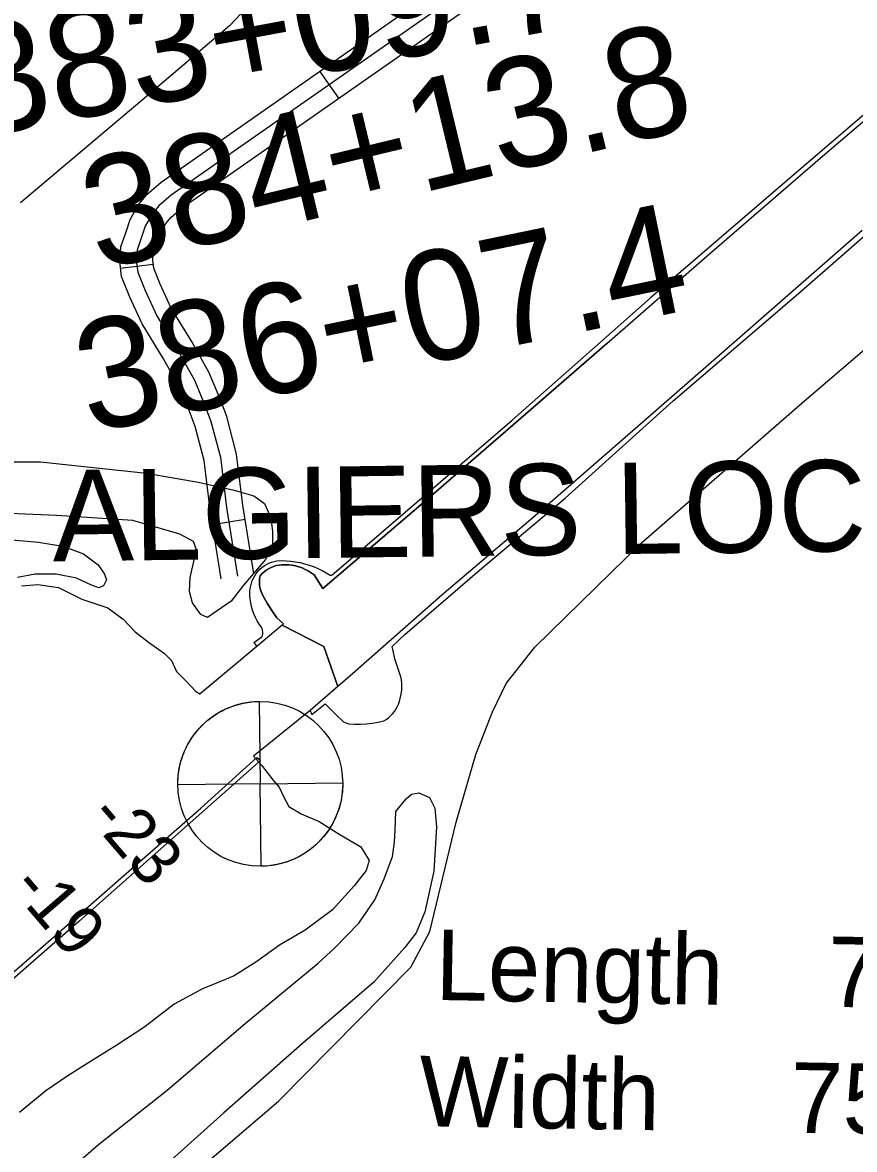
# Model space of a CAD drawing. Extents: x 3704301 to 3742427, y 506229 to 532009.
# Drawn here: x 3711457 to 3712214, y 516437 to 517461 of the extents above; entities that cross this region are included whole.
import ezdxf

# ---------------------------------------------------------------- set-up
doc = ezdxf.new("R2010")
doc.units = 0
for name, color, linetype in [('V-LEVE-TOET', 7, 'Continuous'), ('V-RIVR-GAGE', 7, 'Continuous'), ('V-RIVR-IDEN', 7, 'Continuous'), ('V-ROAD-CNTR', 7, 'Continuous'), ('V-SITE-VEGE', 7, 'Continuous'), ('V-SURV-IDEN', 7, 'Continuous'), ('V-TOPO-SHOR', 7, 'Continuous'), ('V-TOPO-SPOT', 7, 'Continuous'), ('V-TRAN-LOCK', 7, 'Continuous')]:
    doc.layers.add(name, color=color, linetype=linetype)

msp = doc.modelspace()

# ---------------------------------------------------------------- linework, layer by layer
at = {"layer": 'V-LEVE-TOET'}
for points in [[(3711361.398, 517061.842), (3711473.166, 517061.69), (3711569.7060000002, 517051.651), (3711616.72, 517043.39400000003), (3711648.083, 517036.238), (3711667.363, 517030.829), (3711677.003, 517024.028), (3711682.733, 517010.77900000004), (3711684.282, 516998.579), (3711684.427, 516986.416), (3711677.992, 516973.02400000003), (3711657.965, 516949.753), (3711646.588, 516935.042), (3711625.1520000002, 516920.17600000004), (3711619.149, 516923.139), (3711611.477, 516933.63300000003), (3711608.946, 516943.988), (3711609.2800000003, 516956.60500000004), (3711611.901, 516967.292), (3711615.088, 516981.706), (3711612.483, 516989.257), (3711600.037, 516996.134), (3711557.339, 517008.487), (3711487.7800000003, 517013.134), (3711360.716, 517018.369)], [(3711424.006, 516352.617), (3711525.9590000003, 516441.114), (3711588.528, 516490.434), (3711659.3510000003, 516551.224), (3711725.807, 516606.053), (3711740.665, 516619.691), (3711762.782, 516642.487), (3711777.372, 516663.614), (3711785.822, 516682.565), (3711793.377, 516702.94200000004), (3711795.126, 516715.99), (3711795.89, 516727.195), (3711796.3340000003, 516744.01900000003), (3711805.99, 516755.455), (3711810.774, 516759.537), (3711817.355, 516760.765), (3711827.0700000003, 516756.766), (3711831.951, 516746.816), (3711833.3740000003, 516729.943), (3711830.9080000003, 516689.79000000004), (3711822.911, 516652.588), (3711814.926, 516633.626), (3711804.751, 516620.332), (3711776.325, 516588.815), (3711711.715, 516533.003), (3711639.895, 516469.9), (3711568.039, 516405.392)]]:
    msp.add_lwpolyline(points, dxfattribs=at)
at = {"layer": 'V-RIVR-GAGE'}
for points in [[(3711672.2740780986, 516844.07543143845), (3711673.188, 516769.081), (3711598.1935685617, 516768.16707809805), (3711598.197927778, 516770.27128745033), (3711598.282565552, 516772.84550994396), (3711598.493100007, 516775.8392977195), (3711598.821027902, 516778.80151366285), (3711599.2362403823, 516781.57677934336), (3711599.802894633, 516784.5629060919), (3711600.397397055, 516787.1513426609), (3711601.0304314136, 516789.5322333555), (3711601.760019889, 516791.9503033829), (3711602.696632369, 516794.6959204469), (3711603.5989879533, 516797.05209115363), (3711604.575825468, 516799.36916656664), (3711605.74128479, 516801.8825550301), (3711607.1371678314, 516804.60876715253), (3711608.455638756, 516806.95800797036), (3711609.8253245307, 516809.20786549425), (3711612.1858010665, 516812.7118895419), (3711613.8535987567, 516814.954379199), (3711616.0418616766, 516817.6542450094), (3711618.1569687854, 516820.03819591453), (3711619.9720573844, 516821.92945432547), (3711622.707339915, 516824.5489799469), (3711625.021880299, 516826.57033414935), (3711627.4552527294, 516828.5241313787), (3711630.5400670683, 516830.7738888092), (3711632.8971613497, 516832.3397277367), (3711635.465288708, 516833.9041381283), (3711638.420619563, 516835.53627186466), (3711641.0428870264, 516836.8433228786), (3711643.619900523, 516838.0068117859), (3711647.233619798, 516839.4469541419), (3711650.461352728, 516840.5553683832), (3711653.624259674, 516841.4849794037), (3711656.8687691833, 516842.2835750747), (3711660.2607910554, 516842.9589591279), (3711664.3058490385, 516843.5532948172), (3711667.291471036, 516843.84869842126), (3711669.8357466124, 516844.0057136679)], [(3711674.1019219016, 516694.0865685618), (3711673.188, 516769.081), (3711748.1824314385, 516769.9949219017), (3711748.1677877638, 516767.3395463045), (3711748.0273076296, 516764.1775996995), (3711747.8129110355, 516761.5827944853), (3711747.5036555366, 516758.9758324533), (3711747.0107994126, 516755.842594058), (3711746.4073916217, 516752.8360179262), (3711745.5879239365, 516749.50478486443), (3711744.9711220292, 516747.3511088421), (3711744.039971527, 516744.48554943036), (3711742.954575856, 516741.55710577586), (3711741.8916573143, 516738.99996358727), (3711740.738111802, 516736.49372083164), (3711739.491097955, 516734.02534191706), (3711738.178955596, 516731.64917621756), (3711736.5742228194, 516728.9914242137), (3711735.1053372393, 516726.75735905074), (3711733.02345498, 516723.8627750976), (3711730.9196861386, 516721.2049420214), (3711728.3305605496, 516718.24517215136), (3711726.0690134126, 516715.89643939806), (3711723.613273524, 516713.56234137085), (3711721.4570883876, 516711.67692691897), (3711719.83312458, 516710.3510394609), (3711717.2062296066, 516708.35688104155), (3711715.3112859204, 516707.0276912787), (3711712.8148844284, 516705.4041505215), (3711710.1738112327, 516703.83485087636), (3711707.4743774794, 516702.376848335), (3711705.365915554, 516701.33507805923), (3711703.109257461, 516700.30850304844), (3711700.508161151, 516699.2337272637), (3711697.811097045, 516698.2377879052), (3711694.5506475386, 516697.1879793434), (3711691.4019108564, 516696.3265460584), (3711688.979610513, 516695.761986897), (3711686.2309688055, 516695.22345299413), (3711683.8494353, 516694.842404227), (3711681.065456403, 516694.49545394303), (3711678.871715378, 516694.2967070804), (3711676.3033684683, 516694.1453989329)]]:
    msp.add_lwpolyline(points, close=True, dxfattribs=at)
msp.add_circle((3711673.188014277, 516769.0810236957), 74.99999999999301, dxfattribs=at)
at = {"layer": 'V-ROAD-CNTR'}
for p, q in [((3711727.190506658, 517416.9751398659), (3711744.3884722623, 517392.394189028)), ((3711546.105868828, 517237.8744980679), (3711575.8698093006, 517241.63449054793)), ((3711629.7847014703, 517004.91496398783), (3711659.4076422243, 517009.65495450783))]:
    msp.add_line(p, q, dxfattribs=at)
for points in [[(3711637.68468567, 516955.543062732), (3711627.6517057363, 517018.24493732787), (3711622.1367167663, 517063.14184753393), (3711614.017733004, 517094.01678578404), (3711608.6527437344, 517108.5667566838), (3711599.7897614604, 517129.44271493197), (3711585.27479049, 517155.3806630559), (3711565.721829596, 517187.4015990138), (3711554.640851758, 517211.5785506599), (3711547.0558669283, 517230.35551310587), (3711545.30487043, 517244.21448538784), (3711546.278868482, 517257.2484593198), (3711551.097858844, 517270.99743182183), (3711554.8598513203, 517282.25940929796), (3711562.418836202, 517295.445382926), (3711570.0708208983, 517304.9013640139), (3711583.017795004, 517316.10834159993), (3711893.106174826, 517533.05490770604)], [(3711901.7051576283, 517520.7639322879), (3711592.24977654, 517304.2603652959), (3711580.8937992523, 517294.43138495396), (3711574.83481137, 517286.94339993), (3711568.6148238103, 517276.09242163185), (3711565.28983046, 517266.140441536), (3711561.08983886, 517254.15646550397), (3711560.375840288, 517244.59948461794), (3711561.6938376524, 517234.167505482), (3711568.4198242, 517217.51553878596), (3711578.9868030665, 517194.459584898), (3711598.2257645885, 517162.954647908), (3711613.277734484, 517136.0557017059), (3711622.601715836, 517114.09574562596), (3711628.340704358, 517098.52877675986), (3711636.901687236, 517065.9768418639), (3711642.5066760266, 517020.34493312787), (3711652.496656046, 516957.913057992)], [(3711667.308626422, 516960.283053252), (3711657.361646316, 517022.44492892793), (3711651.6666577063, 517068.81183619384), (3711642.663675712, 517103.040767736), (3711636.550687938, 517119.6247345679), (3711626.765707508, 517142.6686884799), (3711611.1767386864, 517170.5286327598), (3711592.251776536, 517201.5175707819), (3711582.1987966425, 517223.452526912), (3711576.3318083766, 517237.9794978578), (3711575.4468101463, 517244.98448384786), (3711575.9008092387, 517251.06447168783), (3711579.4818020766, 517261.2834512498), (3711582.3697963, 517269.9254339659), (3711587.2507865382, 517278.441416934), (3711591.716777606, 517283.9614058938), (3711601.481758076, 517292.41238899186), (3711910.30414043, 517508.47295686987)]]:
    msp.add_lwpolyline(points, dxfattribs=at)
at = {"layer": 'V-SITE-VEGE'}
for points in [[(3711455.682, 517839.613), (3711703.711, 517815.229), (3711879.18, 517797.80700000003), (3711910.707, 517793.721), (3711923.197, 517792.56), (3711932.123, 517789.61100000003), (3711937.492, 517783.67600000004), (3711938.095, 517779.514), (3711930.992, 517765.22500000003), (3711904.88, 517743.16000000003), (3711768.995, 517620.93), (3711706.679, 517569.045), (3711704.313, 517563.688), (3711703.1520000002, 517551.791), (3711704.967, 517539.309), (3711700.238, 517526.216), (3711677.13, 517492.264), (3711645.099, 517458.292), (3711569.731, 517393.88800000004), (3711455.1920000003, 517297.28)], [(3711524.872, 516339.63300000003), (3711689.684, 516480.636), (3711809.984, 516602.387), (3711827.347, 516634.928), (3711851.186, 516734.09), (3711869.3170000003, 516795.684), (3711884.49, 516834.571), (3711896.954, 516860.17100000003), (3711922.974, 516893.271), (3712019.7770000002, 516988.141), (3712166.154, 517115.489), (3712235.302, 517174.947)], [(3711447.1010000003, 516991.063), (3711471.486, 516988.743), (3711493.498, 516985.228), (3711512.545, 516978.13800000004), (3711525.65, 516968.06), (3711531.6180000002, 516959.751), (3711533.414, 516954.402), (3711530.452, 516949.042), (3711526.2970000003, 516947.248), (3711519.748, 516949.609), (3711506.055, 516956.12), (3711487.612, 516959.645), (3711468.5840000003, 516959.598), (3711452.534, 516956.587)]]:
    msp.add_lwpolyline(points, dxfattribs=at)
at = {"layer": 'V-TOPO-SHOR'}
for points in [[(3711456.049, 516949.001), (3711470.915, 516950.38800000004), (3711489.818, 516947.514), (3711510.89, 516936.873), (3711534.411, 516929.134), (3711548.37, 516918.681), (3711559.333, 516907.12), (3711571.546, 516897.89900000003), (3711586.097, 516887.43), (3711592.46, 516881.331), (3711596.935, 516871.13), (3711606.183, 516861.988), (3711614.2630000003, 516853.47000000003), (3711618.348, 516850.99), (3711618.498, 516850.84500000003)], [(3711731.011, 516894.037), (3711693.1070000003, 516913.362), (3711670.171, 516893.908), (3711618.498, 516850.84500000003)], [(3711731.011, 516894.037), (3711743.762, 516857.511), (3711718.412, 516835.73000000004), (3711666.995, 516794.148)], [(3711666.995, 516794.148), (3711674.165, 516786.04600000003), (3711684.489, 516772.724), (3711690.241, 516766.047), (3711694.1720000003, 516757.63800000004), (3711699.271, 516748.606), (3711710.361, 516741.789), (3711726.784, 516734.83), (3711745.453, 516723.066), (3711764.7290000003, 516711.88), (3711772.106, 516699.227), (3711769.4990000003, 516690.4), (3711758.454, 516676.457), (3711738.892, 516654.435), (3711714.088, 516636.112), (3711690.596, 516622.499), (3711670.034, 516607.62), (3711649.521, 516594.521), (3711633.33, 516587.832), (3711620.741, 516582.827), (3711594.862, 516568.683), (3711568.218, 516548.036), (3711542.867, 516531.506), (3711516.333, 516515.007), (3711498.237, 516503.623), (3711478.3000000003, 516489.91500000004), (3711454.06, 516470.39)]]:
    msp.add_lwpolyline(points, dxfattribs=at)
at = {"layer": 'V-TRAN-LOCK'}
msp.add_line((3711667.316, 516897.525), (3711670.171, 516893.908), dxfattribs=at)
for points in [[(3711988.387, 517169.27400000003), (3712079.742, 517249.009), (3712184.389, 517339.62200000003), (3712280.532, 517421.594), (3712368.312, 517500.243), (3712470.534, 517588.555), (3712467.6580000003, 517591.586), (3712413.237, 517545.15400000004), (3712332.779, 517475.177), (3712252.272, 517403.43), (3712133.14, 517301.378), (3712027.901, 517210.783), (3711982.522, 517170.609)], [(3712220.52, 517272.212), (3712111.611, 517176.985), (3712019.044, 517096.101), (3711925.278, 517014.656), (3711838.214, 516940.717), (3711757.117, 516868.98600000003), (3711743.762, 516857.511), (3711731.011, 516894.037), (3711693.1070000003, 516913.362), (3711694.3170000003, 516914.511), (3711688.3510000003, 516919.875), (3711683.835, 516926.553), (3711679.559, 516933.391), (3711675.531, 516940.375), (3711674.472, 516942.417), (3711673.616, 516944.549), (3711672.969, 516946.757), (3711672.541, 516949.016), (3711672.336, 516951.303), (3711672.35, 516953.601), (3711672.592, 516955.889), (3711673.051, 516958.141), (3711674.7320000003, 516960.04000000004), (3711676.583, 516961.775), (3711678.586, 516963.327), (3711680.728, 516964.691), (3711682.985, 516965.846), (3711685.341, 516966.786), (3711687.776, 516967.501), (3711690.264, 516967.98600000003), (3711692.787, 516968.238), (3711695.916, 516968.299), (3711699.038, 516968.13800000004), (3711702.14, 516967.755), (3711705.208, 516967.155), (3711708.227, 516966.342), (3711711.1780000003, 516965.311), (3711714.052, 516964.077), (3711716.8310000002, 516962.641), (3711719.501, 516961.017), (3711722.049, 516959.204), (3711729.975, 516946.60500000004), (3711821.7290000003, 517025.007), (3711903.244, 517095.419), (3711988.387, 517169.27400000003), (3712079.742, 517249.011), (3712184.389, 517339.62200000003), (3712280.532, 517421.594)], [(3711720.089, 516832.13800000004), (3711732.166, 516841.86600000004), (3711741.958, 516832.15), (3711748.8740000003, 516825.468), (3711753.551, 516823.569), (3711758.915, 516823.369), (3711764.285, 516823.428), (3711769.642, 516823.75), (3711774.98, 516824.331), (3711780.284, 516825.173), (3711785.539, 516826.271), (3711787.745, 516827.62200000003), (3711789.825, 516829.162), (3711791.7630000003, 516830.879), (3711793.543, 516832.757), (3711795.1520000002, 516834.784), (3711796.58, 516836.945), (3711797.813, 516839.218), (3711798.843, 516841.594), (3711799.66, 516844.049), (3711800.2600000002, 516846.566), (3711800.997, 516849.329), (3711801.526, 516852.141), (3711801.839, 516854.982), (3711801.935, 516857.841), (3711801.816, 516860.69800000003), (3711801.483, 516863.538), (3711800.934, 516866.346), (3711800.174, 516869.103), (3711799.207, 516871.794), (3711797.284, 516877.229), (3711795.646, 516882.759), (3711794.296, 516888.364), (3711793.242, 516894.03500000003), (3711804.759, 516904.95900000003), (3711872.503, 516963.452), (3711950.475, 517028.765), (3712048.562, 517117.18700000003), (3712162.86, 517215.229), (3712275.994, 517313.889)], [(3712220.518, 517272.212), (3712111.611, 517176.985), (3712019.044, 517096.101), (3711925.278, 517014.656), (3711838.214, 516940.717), (3711757.117, 516868.98600000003), (3711718.412, 516835.73000000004), (3711720.089, 516832.13800000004)], [(3711667.316, 516897.525), (3711674.531, 516902.643), (3711675.082, 516904.076), (3711675.3910000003, 516905.582), (3711675.455, 516907.118), (3711675.271, 516908.641), (3711674.84, 516910.11600000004), (3711674.177, 516911.50200000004), (3711672.151, 516914.357), (3711670.329, 516917.34500000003), (3711668.717, 516920.452), (3711667.3200000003, 516923.663), (3711666.151, 516926.963), (3711665.213, 516930.33400000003), (3711664.508, 516933.762), (3711664.041, 516937.231), (3711663.816, 516940.72500000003), (3711663.832, 516944.22500000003), (3711664.054, 516946.701), (3711664.4820000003, 516949.151), (3711665.115, 516951.555), (3711665.948, 516953.898), (3711666.9760000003, 516956.161), (3711668.193, 516958.33), (3711669.585, 516960.39), (3711671.148, 516962.325), (3711672.866, 516964.12200000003), (3711674.73, 516965.766), (3711676.727, 516967.251), (3711678.84, 516968.56200000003), (3711681.058, 516969.688), (3711683.362, 516970.626), (3711685.738, 516971.365), (3711688.165, 516971.902), (3711692.427, 516971.994), (3711696.6890000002, 516971.865), (3711700.936, 516971.517), (3711705.163, 516970.94800000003), (3711709.353, 516970.161), (3711713.4990000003, 516969.162), (3711717.586, 516967.945), (3711721.605, 516966.52400000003), (3711725.5470000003, 516964.89400000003), (3711729.397, 516963.063), (3711733.147, 516961.033), (3711736.788, 516958.815), (3711737.8570000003, 516958.934), (3711738.867, 516959.30700000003), (3711739.7600000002, 516959.909), (3711740.483, 516960.708), (3711804.972, 517016.01), (3711902.173, 517099.576), (3711982.522, 517170.609)], [(3711988.387, 517169.27400000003), (3711903.244, 517095.419), (3711821.7290000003, 517025.007), (3711729.975, 516946.60500000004), (3711722.049, 516959.204), (3711719.501, 516961.017), (3711716.8310000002, 516962.643), (3711714.052, 516964.077), (3711711.1780000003, 516965.311), (3711708.227, 516966.34), (3711705.208, 516967.155), (3711702.14, 516967.755), (3711699.038, 516968.13800000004), (3711695.914, 516968.299), (3711692.787, 516968.238), (3711690.264, 516967.98600000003), (3711687.776, 516967.501), (3711685.341, 516966.786), (3711682.985, 516965.846), (3711680.728, 516964.691), (3711678.586, 516963.329), (3711676.583, 516961.775), (3711674.7320000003, 516960.04000000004), (3711673.051, 516958.141), (3711672.592, 516955.889), (3711672.35, 516953.601), (3711672.336, 516951.303), (3711672.541, 516949.01300000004), (3711672.969, 516946.757), (3711673.616, 516944.549), (3711674.472, 516942.417), (3711675.531, 516940.375), (3711679.559, 516933.391), (3711683.835, 516926.553), (3711688.3510000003, 516919.875), (3711694.3170000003, 516914.511), (3711693.1070000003, 516913.362), (3711670.171, 516893.908)], [(3711693.1070000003, 516913.362), (3711731.011, 516894.037), (3711743.762, 516857.511)], [(3711673.477, 516790.363), (3711508.252, 516644.025), (3711318.89, 516478.821), (3711140.4390000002, 516323.968), (3711127.723, 516312.485), (3711124.289, 516316.71400000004), (3711285.782, 516456.058), (3711461.216, 516608.628), (3711619.133, 516746.884), (3711670.196, 516793.011), (3711673.477, 516790.363)]]:
    msp.add_lwpolyline(points, dxfattribs=at)

# ---------------------------------------------------------------- texts
at = {"layer": 'V-RIVR-IDEN'}
msp.add_text('ALGIERS LOCK', height=82.99983199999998, rotation=0.7416967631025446, dxfattribs=at).set_placement((3711484.608294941, 516971.2645475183))
at = {"layer": 'V-SURV-IDEN'}
for s, height, rotation, p in [('383+09.7', 99.99999999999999, 10.511153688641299, (3711414.9387973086, 517356.6706876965)), ('384+13.8', 100, 13.522131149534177, (3711525.877850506, 517235.4889874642)), ('386+07.4', 100.00000000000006, 11.63225269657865, (3711517.290817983, 517087.690407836))]:
    msp.add_text(s, height=height, rotation=rotation, dxfattribs=at).set_placement(p)
at = {"layer": 'V-TOPO-SPOT'}
for s, p in [('-23', (3711515.417603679, 516738.7795124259)), ('-19', (3711444.9822263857, 516674.1653258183))]:
    msp.add_text(s, height=45, rotation=310.7207321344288, dxfattribs=at).set_placement(p)
at = {"layer": 'V-TRAN-LOCK'}
for s, p in [("Length    760'", (3711832.128356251, 516572.60770443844)), ("Width     75'", (3711817.368385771, 516457.87693390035))]:
    msp.add_text(s, height=63.99987399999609, rotation=359.00000005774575, dxfattribs=at).set_placement(p)

doc.saveas('drawing.dxf')
